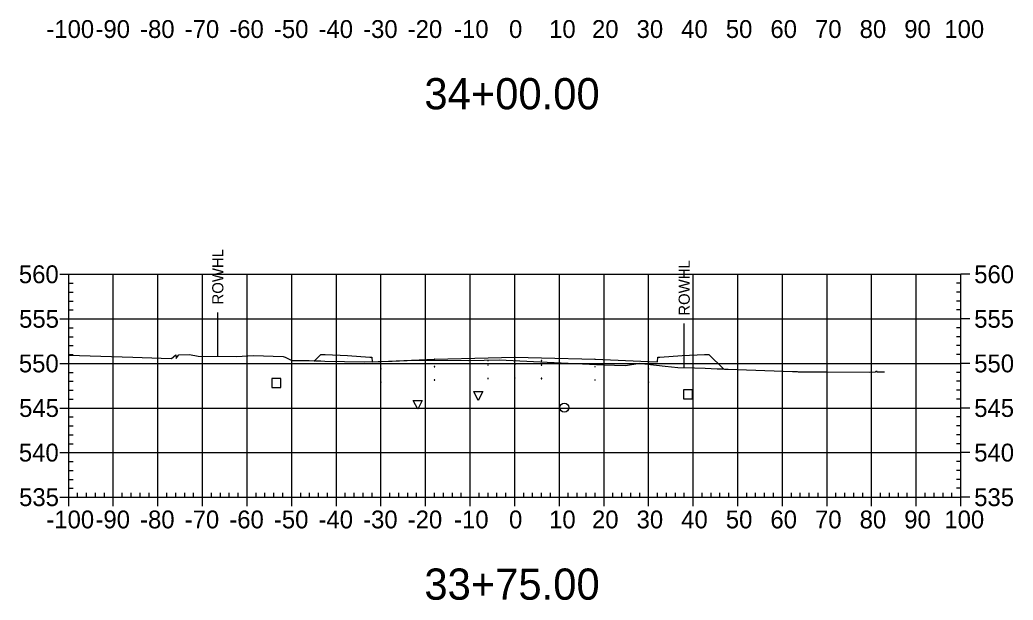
# Model space of a CAD drawing. Extents: x 708103 to 717568, y 374476 to 378707.
# Drawn here: x 710866 to 711088.7, y 376801.5 to 376931.7 of the extents above; entities that cross this region are included whole.
import ezdxf

# ---------------------------------------------------------------- set-up
doc = ezdxf.new("R2010")
doc.units = 0
for name, color, linetype in [('1', 7, 'Continuous'), ('10', 7, 'Continuous'), ('13', 7, 'Continuous'), ('14', 7, 'Continuous'), ('22', 7, 'Continuous'), ('4', 7, 'Continuous'), ('57', 7, 'Continuous'), ('Existing', 7, 'Continuous'), ('XS_Right_of_Way', 7, 'Continuous')]:
    doc.layers.add(name, color=color, linetype=linetype)

msp = doc.modelspace()

# ---------------------------------------------------------------- linework, layer by layer
for points in [[(710970.93, 376855.21), (710971.03, 376855.21), (710971.03, 376855.31), (710970.93, 376855.31)], [(710976.93, 376855.33), (710977.03, 376855.33), (710977.03, 376855.43), (710976.93, 376855.43)], [(710982.93, 376855.21), (710983.03, 376855.21), (710983.03, 376855.31), (710982.93, 376855.31)], [(710946.93, 376853.37), (710947.03, 376853.37), (710947.03, 376853.47), (710946.93, 376853.47)], [(710958.93, 376853.85), (710959.03, 376853.85), (710959.03, 376853.95), (710958.93, 376853.95)], [(710970.93, 376854.21), (710971.03, 376854.21), (710971.03, 376854.31), (710970.93, 376854.31)], [(710976.93, 376854.33), (710977.03, 376854.33), (710977.03, 376854.43), (710976.93, 376854.43)], [(710982.93, 376854.21), (710983.03, 376854.21), (710983.03, 376854.31), (710982.93, 376854.31)], [(710994.93, 376853.85), (710995.03, 376853.85), (710995.03, 376853.95), (710994.93, 376853.95)], [(711006.93, 376853.37), (711007.03, 376853.37), (711007.03, 376853.47), (711006.93, 376853.47)], [(710946.93, 376850.37), (710947.03, 376850.37), (710947.03, 376850.47), (710946.93, 376850.47)], [(710958.93, 376850.85), (710959.03, 376850.85), (710959.03, 376850.95), (710958.93, 376850.95)], [(710970.93, 376851.21), (710971.03, 376851.21), (710971.03, 376851.31), (710970.93, 376851.31)], [(710976.93, 376851.33), (710977.03, 376851.33), (710977.03, 376851.43), (710976.93, 376851.43)], [(710982.93, 376851.21), (710983.03, 376851.21), (710983.03, 376851.31), (710982.93, 376851.31)], [(710994.93, 376850.85), (710995.03, 376850.85), (710995.03, 376850.95), (710994.93, 376850.95)], [(711006.93, 376850.37), (711007.03, 376850.37), (711007.03, 376850.47), (711006.93, 376850.47)]]:
    msp.add_lwpolyline(points, close=True)
at = {"layer": '1'}
for points in [[(710968.78, 376846.34), (710967.78, 376848.34), (710969.78, 376848.34)], [(710955.23, 376844.34), (710954.23, 376846.34), (710956.23, 376846.34)]]:
    msp.add_lwpolyline(points, close=True, dxfattribs=at)
at = {"layer": '10'}
msp.add_lwpolyline([(710922.51, 376849.25), (710924.51, 376849.25), (710924.51, 376851.25), (710922.51, 376851.25)], close=True, dxfattribs=at)
at = {"layer": '13'}
msp.add_circle((710988.1, 376844.73), 1, dxfattribs=at)
at = {"layer": '14'}
for points in [[(710932.07, 376855.22), (710932.07, 376855.27), (710932.07, 376855.22), (710932.02, 376855.22), (710932.07, 376855.22), (710932.07, 376855.17), (710932.07, 376855.22), (710932.12, 376855.22)], [(710946.98, 376855.08), (710946.98, 376855.13), (710946.98, 376855.08), (710946.93, 376855.08), (710946.98, 376855.08), (710946.98, 376855.03), (710946.98, 376855.08), (710947.03, 376855.08)], [(710958.98, 376855.56), (710958.98, 376855.61), (710958.98, 376855.56), (710958.93, 376855.56), (710958.98, 376855.56), (710958.98, 376855.51), (710958.98, 376855.56), (710959.03, 376855.56)], [(710976.98, 376856.04), (710976.98, 376856.09), (710976.98, 376856.04), (710976.93, 376856.04), (710976.98, 376856.04), (710976.98, 376855.99), (710976.98, 376856.04), (710977.03, 376856.04)], [(710994.98, 376855.56), (710994.98, 376855.61), (710994.98, 376855.56), (710994.93, 376855.56), (710994.98, 376855.56), (710994.98, 376855.51), (710994.98, 376855.56), (710995.03, 376855.56)], [(711006.98, 376855.08), (711006.98, 376855.13), (711006.98, 376855.08), (711006.93, 376855.08), (711006.98, 376855.08), (711006.98, 376855.03), (711006.98, 376855.08), (711007.03, 376855.08)], [(711023.75, 376853.38), (711023.75, 376853.43), (711023.75, 376853.38), (711023.7, 376853.38), (711023.75, 376853.38), (711023.75, 376853.33), (711023.75, 376853.38), (711023.8, 376853.38)]]:
    msp.add_lwpolyline(points, dxfattribs=at)
at = {"layer": '22'}
msp.add_lwpolyline([(710932.07, 376855.22), (710933.48, 376856.64), (710934.48, 376856.6), (710939.48, 376856.4), (710944.48, 376856), (710944.9, 376856), (710944.98, 376855), (710946.98, 376855.08), (710958.98, 376855.56), (710970.98, 376855.92), (710976.98, 376856.04), (710982.98, 376855.92), (710994.98, 376855.56), (711006.98, 376855.08), (711008.98, 376855), (711009.07, 376856), (711009.48, 376856), (711014.48, 376856.4), (711019.48, 376856.6), (711020.48, 376856.64), (711023.75, 376853.38)], dxfattribs=at)
at = {"layer": '4'}
msp.add_lwpolyline([(711014.83, 376846.68), (711016.83, 376846.68), (711016.83, 376848.68), (711014.83, 376848.68)], close=True, dxfattribs=at)
at = {"layer": '57'}
for p, q in [((710874.98, 376874.63), (710876.98, 376874.63)), ((710876.98, 376874.63), (711076.98, 376874.63)), ((710876.98, 376824.63), (710876.98, 376874.63)), ((710876.98, 376824.63), (710876.98, 376874.63)), ((710876.98, 376872.63), (710877.98, 376872.63)), ((710886.98, 376824.63), (710886.98, 376874.63)), ((710896.98, 376824.63), (710896.98, 376874.63)), ((710906.98, 376824.63), (710906.98, 376874.63)), ((710916.98, 376824.63), (710916.98, 376874.63)), ((710926.98, 376824.63), (710926.98, 376874.63)), ((710936.98, 376824.63), (710936.98, 376874.63)), ((710946.98, 376824.63), (710946.98, 376874.63)), ((710956.98, 376824.63), (710956.98, 376874.63)), ((710966.98, 376824.63), (710966.98, 376874.63)), ((710976.98, 376824.63), (710976.98, 376874.63)), ((710986.98, 376824.63), (710986.98, 376874.63)), ((710996.98, 376824.63), (710996.98, 376874.63)), ((711006.98, 376824.63), (711006.98, 376874.63)), ((711016.98, 376824.63), (711016.98, 376874.63)), ((711026.98, 376824.63), (711026.98, 376874.63)), ((711036.98, 376824.63), (711036.98, 376874.63)), ((711046.98, 376824.63), (711046.98, 376874.63)), ((711056.98, 376824.63), (711056.98, 376874.63)), ((711066.98, 376824.63), (711066.98, 376874.63)), ((711076.98, 376872.63), (711075.98, 376872.63)), ((711076.98, 376824.63), (711076.98, 376874.63)), ((711076.98, 376824.63), (711076.98, 376874.63)), ((711078.98, 376874.63), (711076.98, 376874.63)), ((710876.98, 376870.63), (710877.98, 376870.63)), ((711076.98, 376870.63), (711075.98, 376870.63)), ((710876.98, 376868.63), (710877.98, 376868.63)), ((711076.98, 376868.63), (711075.98, 376868.63)), ((710876.98, 376866.63), (710877.98, 376866.63)), ((711076.98, 376866.63), (711075.98, 376866.63)), ((710874.98, 376864.63), (710876.98, 376864.63)), ((710876.98, 376864.63), (711076.98, 376864.63)), ((711078.98, 376864.63), (711076.98, 376864.63)), ((710876.98, 376862.63), (710877.98, 376862.63)), ((711076.98, 376862.63), (711075.98, 376862.63)), ((710876.98, 376860.63), (710877.98, 376860.63)), ((711076.98, 376860.63), (711075.98, 376860.63)), ((710876.98, 376858.63), (710877.98, 376858.63)), ((711076.98, 376858.63), (711075.98, 376858.63)), ((710876.98, 376856.63), (710877.98, 376856.63)), ((711076.98, 376856.63), (711075.98, 376856.63)), ((710874.98, 376854.63), (710876.98, 376854.63)), ((710876.98, 376854.63), (711076.98, 376854.63)), ((710876.98, 376852.63), (710877.98, 376852.63)), ((711076.98, 376852.63), (711075.98, 376852.63)), ((711078.98, 376854.63), (711076.98, 376854.63)), ((710876.98, 376850.63), (710877.98, 376850.63)), ((711076.98, 376850.63), (711075.98, 376850.63)), ((710876.98, 376848.63), (710877.98, 376848.63)), ((711076.98, 376848.63), (711075.98, 376848.63)), ((710876.98, 376846.63), (710877.98, 376846.63)), ((711076.98, 376846.63), (711075.98, 376846.63)), ((710874.98, 376844.63), (710876.98, 376844.63)), ((710876.98, 376844.63), (711076.98, 376844.63)), ((711078.98, 376844.63), (711076.98, 376844.63)), ((710876.98, 376842.63), (710877.98, 376842.63)), ((711076.98, 376842.63), (711075.98, 376842.63)), ((710876.98, 376840.63), (710877.98, 376840.63)), ((711076.98, 376840.63), (711075.98, 376840.63)), ((710876.98, 376838.63), (710877.98, 376838.63)), ((711076.98, 376838.63), (711075.98, 376838.63)), ((710876.98, 376836.63), (710877.98, 376836.63)), ((711076.98, 376836.63), (711075.98, 376836.63)), ((710874.98, 376834.63), (710876.98, 376834.63)), ((710876.98, 376834.63), (711076.98, 376834.63)), ((710876.98, 376832.63), (710877.98, 376832.63)), ((711076.98, 376832.63), (711075.98, 376832.63)), ((711078.98, 376834.63), (711076.98, 376834.63)), ((710876.98, 376830.63), (710877.98, 376830.63)), ((711076.98, 376830.63), (711075.98, 376830.63)), ((710876.98, 376828.63), (710877.98, 376828.63)), ((711076.98, 376828.63), (711075.98, 376828.63)), ((710876.98, 376826.63), (710877.98, 376826.63)), ((711076.98, 376826.63), (711075.98, 376826.63)), ((710874.98, 376824.63), (710876.98, 376824.63)), ((710876.98, 376824.63), (711076.98, 376824.63)), ((710876.98, 376824.63), (711076.98, 376824.63)), ((710876.98, 376822.63), (710876.98, 376824.63)), ((710878.98, 376824.63), (710878.98, 376825.63)), ((710880.98, 376824.63), (710880.98, 376825.63)), ((710882.98, 376824.63), (710882.98, 376825.63)), ((710884.98, 376824.63), (710884.98, 376825.63)), ((710886.98, 376822.63), (710886.98, 376824.63)), ((710888.98, 376824.63), (710888.98, 376825.63)), ((710890.98, 376824.63), (710890.98, 376825.63)), ((710892.98, 376824.63), (710892.98, 376825.63)), ((710894.98, 376824.63), (710894.98, 376825.63)), ((710896.98, 376822.63), (710896.98, 376824.63)), ((710898.98, 376824.63), (710898.98, 376825.63)), ((710900.98, 376824.63), (710900.98, 376825.63)), ((710902.98, 376824.63), (710902.98, 376825.63)), ((710904.98, 376824.63), (710904.98, 376825.63)), ((710906.98, 376822.63), (710906.98, 376824.63)), ((710908.98, 376824.63), (710908.98, 376825.63)), ((710910.98, 376824.63), (710910.98, 376825.63)), ((710912.98, 376824.63), (710912.98, 376825.63)), ((710914.98, 376824.63), (710914.98, 376825.63)), ((710916.98, 376822.63), (710916.98, 376824.63)), ((710918.98, 376824.63), (710918.98, 376825.63)), ((710920.98, 376824.63), (710920.98, 376825.63)), ((710922.98, 376824.63), (710922.98, 376825.63)), ((710924.98, 376824.63), (710924.98, 376825.63)), ((710926.98, 376822.63), (710926.98, 376824.63)), ((710928.98, 376824.63), (710928.98, 376825.63)), ((710930.98, 376824.63), (710930.98, 376825.63)), ((710932.98, 376824.63), (710932.98, 376825.63)), ((710934.98, 376824.63), (710934.98, 376825.63)), ((710936.98, 376822.63), (710936.98, 376824.63)), ((710938.98, 376824.63), (710938.98, 376825.63)), ((710940.98, 376824.63), (710940.98, 376825.63)), ((710942.98, 376824.63), (710942.98, 376825.63)), ((710944.98, 376824.63), (710944.98, 376825.63)), ((710946.98, 376822.63), (710946.98, 376824.63)), ((710948.98, 376824.63), (710948.98, 376825.63)), ((710950.98, 376824.63), (710950.98, 376825.63)), ((710952.98, 376824.63), (710952.98, 376825.63)), ((710954.98, 376824.63), (710954.98, 376825.63)), ((710956.98, 376822.63), (710956.98, 376824.63)), ((710958.98, 376824.63), (710958.98, 376825.63)), ((710960.98, 376824.63), (710960.98, 376825.63)), ((710962.98, 376824.63), (710962.98, 376825.63)), ((710964.98, 376824.63), (710964.98, 376825.63)), ((710966.98, 376822.63), (710966.98, 376824.63)), ((710968.98, 376824.63), (710968.98, 376825.63)), ((710970.98, 376824.63), (710970.98, 376825.63)), ((710972.98, 376824.63), (710972.98, 376825.63)), ((710974.98, 376824.63), (710974.98, 376825.63)), ((710976.98, 376822.63), (710976.98, 376824.63)), ((710978.98, 376824.63), (710978.98, 376825.63)), ((710980.98, 376824.63), (710980.98, 376825.63)), ((710982.98, 376824.63), (710982.98, 376825.63)), ((710984.98, 376824.63), (710984.98, 376825.63)), ((710986.98, 376822.63), (710986.98, 376824.63)), ((710988.98, 376824.63), (710988.98, 376825.63)), ((710990.98, 376824.63), (710990.98, 376825.63)), ((710992.98, 376824.63), (710992.98, 376825.63)), ((710994.98, 376824.63), (710994.98, 376825.63)), ((710996.98, 376822.63), (710996.98, 376824.63)), ((710998.98, 376824.63), (710998.98, 376825.63)), ((711000.98, 376824.63), (711000.98, 376825.63)), ((711002.98, 376824.63), (711002.98, 376825.63)), ((711004.98, 376824.63), (711004.98, 376825.63)), ((711006.98, 376822.63), (711006.98, 376824.63)), ((711008.98, 376824.63), (711008.98, 376825.63)), ((711010.98, 376824.63), (711010.98, 376825.63)), ((711012.98, 376824.63), (711012.98, 376825.63)), ((711014.98, 376824.63), (711014.98, 376825.63)), ((711016.98, 376822.63), (711016.98, 376824.63)), ((711018.98, 376824.63), (711018.98, 376825.63)), ((711020.98, 376824.63), (711020.98, 376825.63)), ((711022.98, 376824.63), (711022.98, 376825.63)), ((711024.98, 376824.63), (711024.98, 376825.63)), ((711026.98, 376822.63), (711026.98, 376824.63)), ((711028.98, 376824.63), (711028.98, 376825.63)), ((711030.98, 376824.63), (711030.98, 376825.63)), ((711032.98, 376824.63), (711032.98, 376825.63)), ((711034.98, 376824.63), (711034.98, 376825.63)), ((711036.98, 376822.63), (711036.98, 376824.63)), ((711038.98, 376824.63), (711038.98, 376825.63)), ((711040.98, 376824.63), (711040.98, 376825.63)), ((711042.98, 376824.63), (711042.98, 376825.63)), ((711044.98, 376824.63), (711044.98, 376825.63)), ((711046.98, 376822.63), (711046.98, 376824.63)), ((711048.98, 376824.63), (711048.98, 376825.63)), ((711050.98, 376824.63), (711050.98, 376825.63)), ((711052.98, 376824.63), (711052.98, 376825.63)), ((711054.98, 376824.63), (711054.98, 376825.63)), ((711056.98, 376822.63), (711056.98, 376824.63)), ((711058.98, 376824.63), (711058.98, 376825.63)), ((711060.98, 376824.63), (711060.98, 376825.63)), ((711062.98, 376824.63), (711062.98, 376825.63)), ((711064.98, 376824.63), (711064.98, 376825.63)), ((711066.98, 376822.63), (711066.98, 376824.63)), ((711068.98, 376824.63), (711068.98, 376825.63)), ((711070.98, 376824.63), (711070.98, 376825.63)), ((711072.98, 376824.63), (711072.98, 376825.63)), ((711074.98, 376824.63), (711074.98, 376825.63)), ((711076.98, 376822.63), (711076.98, 376824.63)), ((711078.98, 376824.63), (711076.98, 376824.63))]:
    msp.add_line(p, q, dxfattribs=at)
at = {"layer": 'Existing'}
msp.add_lwpolyline([(710876.98, 376856.47), (710891.35, 376856.01), (710897.74, 376855.83), (710900.05, 376855.73), (710900.96, 376856.58), (710901.06, 376855.72), (710901.16, 376855.91), (710901.7, 376856.59), (710904.02, 376856.65), (710905.98, 376856.26), (710906, 376856.26), (710914.6, 376856.19), (710918.4, 376856.43), (710925.03, 376856.19), (710925.53, 376856.02), (710926.99, 376855.32), (710927.82, 376855.3), (710928.92, 376855.28), (710929.91, 376855.26), (710930.89, 376855.25), (710932.28, 376855.22), (710933.47, 376855.18), (710934.37, 376855.14), (710943.25, 376854.95), (710949.51, 376855.13), (710954.51, 376855.33), (710958.18, 376855.39), (710966.7, 376855.3), (710973.52, 376855.44), (710984.26, 376854.9), (710996.85, 376854.34), (711001.77, 376854.19), (711004.53, 376854.65), (711004.96, 376854.7), (711006.17, 376854.52), (711010.68, 376854.04), (711013.51, 376853.74), (711017.24, 376853.64), (711019.67, 376853.55), (711021.01, 376853.49), (711022.34, 376853.44), (711023.5, 376853.39), (711024, 376853.37), (711024.44, 376853.35), (711024.81, 376853.33), (711039.23, 376852.84), (711039.52, 376852.83), (711039.95, 376852.81), (711040.27, 376852.79), (711040.5, 376852.78), (711040.67, 376852.77), (711043.48, 376852.72), (711047.04, 376852.71), (711056.43, 376852.69), (711057.87, 376852.76), (711058.08, 376852.94), (711058.12, 376852.77), (711059.84, 376852.71)], dxfattribs=at)
at = {"layer": 'XS_Right_of_Way'}
for p, q in [((710910.33, 376866.09), (710910.33, 376856.09)), ((711014.89, 376863.57), (711014.89, 376853.57))]:
    msp.add_line(p, q, dxfattribs=at)

# ---------------------------------------------------------------- texts
at = {"layer": '1'}
for s, p in [('34+00.00', (710956.71, 376911.63)), ('33+75.00', (710956.71, 376801.63))]:
    msp.add_text(s, height=7, dxfattribs=at).set_placement(p)
at = {"layer": '14'}
for p in [(710934.45, 376856.55), (710934.45, 376855.89), (710939.45, 376855.69), (711014.45, 376855.69), (711019.45, 376856.55), (711019.45, 376855.89)]:
    msp.add_text('+', height=0.1, dxfattribs=at).set_placement(p)
at = {"layer": '57'}
for s, p in [('-100', (710871.97, 376927.63)), ('-90', (710882.98, 376927.63)), ('-80', (710892.98, 376927.63)), ('-70', (710902.98, 376927.63)), ('-60', (710912.98, 376927.63)), ('-50', (710922.98, 376927.63)), ('-40', (710932.98, 376927.63)), ('-30', (710942.98, 376927.63)), ('-20', (710952.98, 376927.63)), ('-10', (710963.37, 376927.63)), ('0', (710975.69, 376927.63)), ('10', (710984.68, 376927.63)), ('20', (710994.29, 376927.63)), ('30', (711004.29, 376927.63)), ('40', (711014.29, 376927.63)), ('50', (711024.29, 376927.63)), ('60', (711034.29, 376927.63)), ('70', (711044.29, 376927.63)), ('80', (711054.29, 376927.63)), ('90', (711064.29, 376927.63)), ('100', (711073.28, 376927.63)), ('560', (710865.81, 376872.63)), ('560', (711079.98, 376872.63)), ('555', (710865.86, 376862.63)), ('555', (711079.98, 376862.63)), ('550', (710865.81, 376852.63)), ('550', (711079.98, 376852.63)), ('545', (710865.86, 376842.63)), ('545', (711079.98, 376842.63)), ('540', (710865.81, 376832.63)), ('540', (711079.98, 376832.63)), ('535', (710865.86, 376822.63)), ('535', (711079.98, 376822.63)), ('-100', (710871.97, 376817.63)), ('-90', (710882.98, 376817.63)), ('-80', (710892.98, 376817.63)), ('-70', (710902.98, 376817.63)), ('-60', (710912.98, 376817.63)), ('-50', (710922.98, 376817.63)), ('-40', (710932.98, 376817.63)), ('-30', (710942.98, 376817.63)), ('-20', (710952.98, 376817.63)), ('-10', (710963.37, 376817.63)), ('0', (710975.69, 376817.63)), ('10', (710984.68, 376817.63)), ('20', (710994.29, 376817.63)), ('30', (711004.29, 376817.63)), ('40', (711014.29, 376817.63)), ('50', (711024.29, 376817.63)), ('60', (711034.29, 376817.63)), ('70', (711044.29, 376817.63)), ('80', (711054.29, 376817.63)), ('90', (711064.29, 376817.63)), ('100', (711073.28, 376817.63))]:
    msp.add_text(s, height=4, dxfattribs=at).set_placement(p)
at = {"layer": 'XS_Right_of_Way'}
for p in [(710911.65, 376867.85), (711016.21, 376865.33)]:
    msp.add_text('ROWHL', height=2.5, rotation=90, dxfattribs=at).set_placement(p)

doc.saveas('drawing.dxf')
